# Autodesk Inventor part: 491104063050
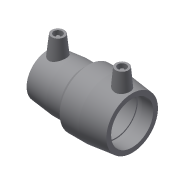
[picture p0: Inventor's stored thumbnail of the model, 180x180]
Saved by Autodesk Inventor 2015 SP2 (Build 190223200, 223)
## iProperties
Created: 2017-06
Part Number: 491104063050
Material: Generic
Description: PLASSON REDUCING COUPLER 63-50
Document SubType Name: Modeling
Designer: KIM
Mass: 54.8237 g
Surface Area: 155.252 cm^2
Volume: 54.8237 cm^3
Density: 1 g/cm^3
Appearance: Default
Author: KIM
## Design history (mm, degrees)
derived "491104.ipt"
feature "Solid1::491104.ipt"
tag "TaggingFeature1"
body "Solid1"
other parameters: "d0" = 119, "d2" = 68, "d3" = 49, "d4" = 29.4, "d5" = 61.2, "d8" = 168 deg, "d10" = 19.6, "d11" = 6.53333, "d13" = 119, "d14" = 17.6296, "d15" = 49, "d19" = 2.45, "d20" = 168 deg, "d22" = 108.92847, "d25" = 135 deg, "d29" = 54, "d30" = 15, "d31" = 45.22, "d34" = 6 deg, "d35" = 15, "d38" = 26.5, "d39" = 5 deg, "d41" = 4, "d42" = 14, "d43" = 0, "d45" = 4, "d46" = 14, "d47" = 0, "d48" = 68, "d49" = 63, "d50" = 82, "d52" = 45, "d53" = 22.8, "d54" = 7.6, "d55" = 168 deg, "d56" = 34.2, "d57" = 57, "d58" = 73.8, "d59" = 2.45, "d60" = 135 deg, "d61" = 59, "d62" = 15, "d64" = 4, "d66" = 5 deg, "d67" = 14, "d68" = 0, "d69" = 45.22, "d70" = 68, "d71" = 82, "d73" = 77.08, "d76" = 2.45, "d77" = 168 deg, "d78" = 63, "d79" = 2.45, "d80" = 57, "d81" = 45, "d82" = 63.92, "d83" = 120 deg, "d88" = 15, "d89" = 24.35, "d90" = 5 deg, "d92" = 4, "d93" = 14, "d94" = 0, "d95" = 3, "d96" = 0, "d97" = 3, "d98" = 0, "d99" = 14.21, "d100" = 3.5525, "d101" = 62.0024, "d102" = 20 deg, "d103" = 16.53, "d104" = 4.1325, "d105" = 74.7676, "d106" = 3.60705, "d107" = 3, "d108" = 0, "d109" = 3, "d110" = 0, "L_" = 119, "L_2" = 49, "D_1" = 68, "A_1" = 54, "d_2" = 12, "L_1" = 57, "d_" = 63, "A_" = 59, "D_" = 82
